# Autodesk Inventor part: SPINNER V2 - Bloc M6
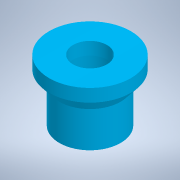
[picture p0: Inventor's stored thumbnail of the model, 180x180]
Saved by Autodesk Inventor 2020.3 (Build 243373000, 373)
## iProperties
Created: 2015-08
Part Number: SPINNER V2 - Bloc M6
Material: solidworks materials|Alliage 1060
Document SubType Name: Modeling
Designer: ficho
Density: 2.7 g/cm^3
Appearance: 221,232,255
Sending System: SolidWorks 2014
Last Author: Guillaume
Last Saved: 2015-08-26
Author: ficho
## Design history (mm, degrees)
feature "Révolution1"
node "Solide1"
